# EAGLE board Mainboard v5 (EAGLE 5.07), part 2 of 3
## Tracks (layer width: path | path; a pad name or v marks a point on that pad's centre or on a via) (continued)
GND  (via drill 0.3) (continued)
  Top 0.254: 38.26,59.42 SW2.1 38.31,59.37 v36.99,59.37 | SW1.1 38.26,43.55 v38.26,47.62 38.26,52.12 SW1.2 | R172.1 Q37.E 58.9,41.45 v58.9,40.32 | IC25.2 55.41,136.6 55.41,135.25 | 55.41,135.25 55.41,134.2 IC25.5 | 55.41,135.25 v54.77,135.25 | RESET.2 90.33,112.13 v90.33,113.03 | 98.27,59.69 IC11.2 | Q33.E v54.77,35.88 | IC13.5 60.25,48.49 59.85,48.9 58.9,48.9 58.65,48.65 IC13.3 58.65,46.42 C69.2 v56.67,45.72 | IC13.21 59.45,57.23 C72.2 v58.26,59.69 | C70.2 63.34,59.05 v63.34,60.01 | C135.2 79.53,10.48 v78.58,9.53 | IC37.5 95.81,20.09 95.41,19.68 95.41,18.73 95.66,18.48 IC37.3 98.33,18.48 C137.2 v99.85,18.73 v99.86,18.73 | IC37.21 85.97,19.29 C140.2 | C140.2 D26.2 | C140.2 78.58,20 v75.09,23.5 75.09,24.85 C139.- | C138.2 v85.25,27.3 | C136.2 v95.73,10.16 | v96.05,59.69 98.27,59.69 | v68.74,27.3 IC26.22 | QG1.2 66.82,45.09 v65.56,45.09 | D4.A 83.03,74.16 v83.03,73.03 | C22.2 v2.7,68.9 | IC3.3 v6.19,63.18 | IC4.3 6.53,68.88 7.14,68.26 v7.46,68.26
  Top 0.305: IC1.12 90.97,71.75 v91.6,72.39
  Top 0.406: C80.- 41.61,33.97 v43.34,33.97 | R15.1 IC1.12 | IC7.12 R87.1 | IC2.12 R33.1 v33.5,84.45 | IC5.12 R51.1 v33.5,53.34 | IC6.12 88.11,41.91 R69.1 87.16,40.32 v87.16,39.37
  Top 0.61: v40.16,28.57 40.8,28.57 | 41.12,29.21 R158.1 | v40.16,12.7 41.12,12.7 R168.1 | C23.2 7.46,59.69 ENC2.3 | C34.2 7.46,44.45 ENC3.3 | C11.2 112.88,57.15 ENC1.3 | C45.2 112.88,41.91 ENC4.3 | IC7.12 28.73,112.39 v28.73,111.76 v28.73,108.9
  Top 1.219: C46.A C50.2
  Bottom 0.254: USB.5 77.31,128.91 75.72,128.91 | 75.72,128.91 IC28.2 | 75.72,128.91 73.82,128.91 73.5,129.22 C88.2 73.5,129.86 v73.5,130.81 | C90.2 94.46,124.14 94.46,126.05 | 94.46,126.05 94.46,128.91 94.78,129.22 IC27.10 | 94.46,126.05 IC27.15 | C90.2 v94.78,122.24 92.87,122.24 92.55,122.56 C87.2 | C90.2 | C86.2 90.33,131.13 v89.38,131.13 | C115.2 45.88,29.84 v45.88,29.53 | R159.1 51.59,30.48 51.91,30.48 v51.91,28.89 SJ1.1 | C120.2 45.88,13.97 v45.88,13.65 | R173.1 51.91,14.61 v51.91,13.02 SJ2.1 | IC27.8 90.33,129.86 90.65,130.18 C86.2 | C86.2 | C65.2 v27.15,60.33 | R177.1 73.19,8.25 73.19,8.89 v72.87,9.53 | R179.1 v66.2,8.89 | M2.5 7.83,81.01 8.41,81.6 8.41,87.95 v7.46,88.9 | M3.5 9.32,34.34 8.73,34.92 4.92,34.92 v3.97,33.97 | M1.5 112.51,79.01 111.92,78.42 111.92,73.03 v112.87,72.07 | M4.5 108.38,34.34 107.79,34.92 101.44,34.92 100.49,33.97 v98.58,33.97 C74.2 | 10.32,119.38 C53.2 | v6.19,119.38 10.32,119.38 | C55.2 17.94,119.38 14.13,119.38 | 10.32,119.38 14.13,119.38 | 14.13,119.38 C54.2 | C77.2 15.09,90.72 | v107.47,91.44 106.2,91.44 C73.2 107.47,89.53 107.47,87.95 108.11,87.31 IC15.3 108.13,86.68 105.25,86.68 104.61,87.31 IC14.3 | 25.24,116.84 C76.2 | 25.24,116.84 24.29,117.79 24.29,120.02 | 24.29,120.02 23.45,120.02 IC23.3 | 24.29,120.02 24.29,120.65 24.61,120.97 26.51,120.97 27.15,120.33 IC22.3 | 25.24,116.84 v24.29,116.84 | Q31.E v25.24,131.44 | 97.95,112.08 R144.1 | R145.1 97.95,110.17 | R178.1 70.96,8.57 v70.96,9.53 | IC18.3 25.56,33.97 C75.2 23,35.56 IC19.3 v22.7,33.97 | C68.2 v53.5,56.2 | D21.2 55.72,59.69 55.09,59.69 | 55.09,59.69 v58.26,59.69 | R176.1 v77.63,8.89 | QG2.2 94.15,22.23 v93.5,22.23 | IC17.3 v14.13,89.22 14.13,89.53 C77.2
  Bottom 0.254: IC16.3 16.99,89.22 C77.2 | IC20.3 95.72,35.56 C74.2 | IC21.3 98.9,35.56 C74.2 | v86.84,1.59 C143.2 C142.2 C141.2 | D16.A 84.48,47.31 v83.98,47.31 | D12.A 38.9,48.26 v38.26,47.62 | D20.A v33.81,97.47 | D8.A v36.04,76.2 | C71.- 55.09,61.59 55.09,59.69
  Bottom 0.406: 97.95,111.12 97.95,112.08 | 97.95,111.12 103.03,111.12 JTAG.10 | 97.95,110.17 97.95,111.12
  pour Top (no thermals): 52.55,17.14 52.55,20.64 52.23,20.95 52.23,23.5 53.82,23.5 53.82,22.23 55.09,20.95 55.09,17.14
  pour Top (no thermals): 52.55,1.27 52.55,4.76 52.23,5.08 52.23,7.62 53.82,7.62 53.82,6.35 55.09,5.08 55.09,1.27
  pour Top (no thermals): 79.53,15.88 77.95,15.88 77.63,15.56 77.63,15.24 69.06,15.24 68.42,14.61 68.42,14.29 66.83,14.29 66.83,16.83 68.11,16.83 68.42,17.14 68.42,17.46 69.69,17.46 69.69,17.14 70.01,16.83 74.14,16.83 74.45,17.14 74.45,17.46 77.63,17.46 77.95,17.14 79.53,17.14
  pour Top (no thermals): 10.95,97.47 12.86,97.47 12.86,95.57 14.45,93.98 14.45,92.71 10.32,92.71 10.32,93.66 10.95,94.3
  pour Top (no thermals): 10.95,68.26 10.95,65.41 10,64.45 10,63.5 14.13,63.5 14.13,66.99 12.86,68.26
  pour Top (no thermals): 10.95,55.56 10.95,58.42 10.32,59.05 10.32,60.33 14.13,60.33 14.13,56.83 12.86,55.56
  pour Top (no thermals): 109.06,56.83 109.06,59.69 110.02,60.64 110.02,61.59 105.89,61.59 105.89,56.83
  pour Top (no thermals): 109.06,68.26 109.06,65.41 110.02,64.45 110.02,63.5 105.89,63.5 105.89,68.26
  pour GND (no thermals): 0.16,114.94 8.41,123.19 8.41,31.75 14.77,25.4 14.77,20.95 3.97,20.95 0.16,24.77
  pour GND (no thermals): 9.68,118.11 19.84,118.11 19.84,34.92 33.81,20.95 16.04,20.95 16.04,27.3 9.68,33.66
  pour GND (no thermals): 110.65,70.48 100.49,70.48 100.49,37.47 96.68,33.66 65.56,33.66 52.87,20.95 59.22,20.95 67.47,29.21 103.03,29.21 110.65,36.83
  pour GND (no thermals): 111.92,86.36 119.54,86.36 119.54,24.77 95.41,0.64 66.83,0.64 66.83,5.08 60.48,11.43 60.48,20.32 68.11,27.94 104.3,27.94 111.92,35.56
  pour GND (no thermals): 35.72,20.95 21.11,35.56 21.11,119.38 9.68,119.38 9.68,124.46 24.92,139.7 94.14,139.7 119.54,114.3 119.54,87.63 110.65,87.63 110.65,71.75 99.22,71.75 99.22,38.1 96.68,35.56 64.93,35.56 50.33,20.95
  pour GND (no thermals): 5.24,20.95 25.56,0.64 66.83,0.64 66.83,5.08 59.22,12.7 59.22,20.95
HALL-I1  (via drill 0.3)
  Top 0.254: IC29.26 58,102.3 v57.94,102.23
  Bottom 0.254: v57.94,102.23 57.94,101.6 62.07,101.6 63.66,100.01 63.66,91.76 72.55,82.87 77.31,82.87 82.39,87.95 82.39,94.3 83.34,95.25 83.98,95.25 91.6,87.63 100.49,87.63 100.81,87.31 IC14.4
HALL-I2  (via drill 0.3)
  Top 0.254: IC29.28 57,102.86 v56.99,102.23 | v21.11,88.9 29.37,88.9 39.53,99.06 40.8,100.33 v40.8,102.87
  Bottom 0.254: v56.99,102.23 56.99,102.87 47.78,102.87 47.15,103.5 45.88,103.5 45.24,102.87 v40.8,102.87 | IC16.4 20.8,89.22 v21.11,88.9
HALL-I3  (via drill 0.3)
  Top 0.152: IC29.44 49.86,98.59 49.37,98.11 45.24,98.11 43.66,96.52 v43.34,96.52
  Bottom 0.254: v43.34,96.52 43.34,82.55 42.7,81.92 42.7,48.26 38.58,44.13 37.62,43.18 34.45,43.18 34.45,36.83 31.59,33.97 IC18.4
HALL-I4  (via drill 0.3)
  Top 0.254: v57.94,88.9 57.94,100.33 56.36,101.92 56.36,102.87 56.5,103.02 IC29.29 | v74.45,55.88 82.08,48.26 82.08,41.27 84.93,38.42 v91.6,38.42 | v74.45,76.52 68.74,76.52 v68.11,77.15
  Bottom 0.254: v68.11,77.15 57.94,87.31 v57.94,88.9 | v74.45,55.88 v74.45,76.52 | IC20.4 92.23,35.56 91.6,36.2 v91.6,38.42
HALL-I5  (via drill 0.3)
  Top 0.152: IC29.27 57.5,105.22 v57.31,105.41
  Top 0.254: v42.07,111.76 37.62,116.2 v31.27,116.2
  Bottom 0.254: v57.31,105.41 57.31,111.76 v42.07,111.76 | IC22.4 30.96,120.33 31.27,120.02 v31.27,116.2
JTAG-SRST
  Top 0.254: R143.2 JTAG.15
  Top 0.406: JTAG.15 103.03,106.05 103.03,116.2 109.38,116.2 JP1.1
JTAG-TCK
  Top 0.406: R141.2 JTAG.9
  Bottom 0.406: JTAG.9 R144.2
JTAG-TDI
  Top 0.406: R139.2 JTAG.5
  Bottom 0.406: JTAG.5 R130.1
JTAG-TDO
  Top 0.406: R142.2 JTAG.13
  Bottom 0.406: JTAG.13 R128.1
JTAG-TMS
  Top 0.406: R140.2 JTAG.7
  Bottom 0.406: JTAG.7 R129.1
JTAG-TRST
  Top 0.406: R132.2 JTAG.3 103.03,121.28 109.38,121.28 JP1.2
  Bottom 0.254: JTAG.3 R131.1
KD-CS
  Top 0.254: IC29.139 73.4,99.59 73.82,100.01 77.31,100.01 78.27,100.97 112.56,100.97 KD.7
KD-RST
  Top 0.254: IC29.135 73.94,97.59 74.77,98.42 112.56,98.42 KD.9
LED0
  Top 0.254: LED9.C 49.37,105.31 49.37,104.46 50.01,103.82 50.96,103.82 52.55,102.23 52.55,100.97 52.18,100.59 IC29.40
LED1
  Top 0.254: LED8.C 51.06,105.63 52.23,104.46 53.01,104.46 IC29.36
LIS3I-CS  (via drill 0.3)
  Top 0.254: IC29.47 52.92,97.09 53.5,96.52 53.5,93.03 v54.77,91.76 | v63.98,65.09 63.98,66.04 62.71,67.31 62.39,67.63 61.75,67.63 61.6,67.47 IC24.13
  Bottom 0.254: v54.77,91.76 53.18,90.17 53.18,87.95 54.45,86.68 54.45,85.72 54.45,84.45 53.5,84.45 52.23,83.19 52.23,81.92 53.82,80.33 53.82,78.74 53.5,78.42 53.18,78.11 53.18,72.71 53.18,68.9 56.04,66.04 63.03,66.04 v63.98,65.09
LIS3I-RDY  (via drill 0.3)
  Top 0.254: IC29.81 57,80.66 55.72,79.38 v55.72,73.98 | v55.09,68.26 55.22,68.4 IC24.6
  Bottom 0.254: v55.72,73.98 55.72,68.9 v55.09,68.26
LIS3O-CS  (via drill 0.3)
  Top 0.152: IC29.46 50.13,97.59 50.01,97.47 46.52,97.47 45.88,96.84 44.61,95.57 44.29,95.25
  Top 0.254: 44.29,95.25 42.7,95.25 42.39,95.25 42.07,95.57 42.07,96.2 43.98,98.11 v43.98,116.84 | v61.75,130.18 61.6,130.33 IC25.13
  Bottom 0.254: v43.98,116.84 54.14,116.84 59.22,121.92 59.85,122.56 61.75,124.46 v61.75,130.18
LIS3O-RDY  (via drill 0.3)
  Top 0.254: IC29.140 71.2,100.09 v69.69,101.6 | v55.41,133.35 56.35,133.35 IC25.6
  Bottom 0.254: v69.69,101.6 69.06,102.23 69.06,103.5 73.19,107.63 73.19,120.02 59.85,133.35 v55.41,133.35
M1-A  (via drill 0.3)
  Top 0.61: v100.49,83.19 IC1.26 v95.09,83.19
  Bottom 0.61: M1.11 M1.10 | v100.49,83.19 Q1.2 | v95.09,83.19 94.78,83.19 94.14,83.19 C3.2
  other vias: 110.97,86.04 110.97,85.09 110.97,84.14 106.2,85.72 106.2,84.45 106.2,83.19 106.2,81.92 110.02,86.04 110.02,85.09 110.02,84.14
  pour Top (no thermals): 105.89,86.04 111.28,86.04 111.28,83.82 110.33,83.82 109.7,83.19 109.7,81.6 105.89,81.6
  pour Bottom (no thermals): 114.46,83.82 110.02,83.82 110.02,86.36 113.19,86.36 114.46,85.09
  pour Bottom (no thermals): 101.12,84.77 103.98,84.77 103.98,86.04 106.52,86.04 106.52,81.6 101.12,81.6
M1-ADC  (via drill 0.3)
  Top 0.305: 87.79,69.22 C2.2
  Top 0.61: 102.08,68.26 87.79,68.26 87.79,69.22 87.79,70.48 IC1.13 | v100.55,65.72 101.5,66.67 101.76,66.67 R18.1
  Bottom 0.61: v100.55,65.72 100.17,65.72 99.54,65.09 R91.1
  pour Top (no thermals): 101.12,86.04 105.25,86.04 105.25,65.41 101.44,65.41 101.44,68.26 103.98,68.26 103.98,70.17 101.12,70.17 101.12,73.34 103.67,73.34 103.67,76.52 101.12,76.52 101.12,79.69 103.67,79.69 103.67,82.87 101.12,82.87
M1-AOUT  (via drill 0.3)
  Top 0.254: v89.69,66.99 C58.1 | IC13.24 57.05,57.09 56.36,57.78 56.36,59.69 59.53,62.87 v81.44,62.87
  Bottom 0.254: C58.1 v89.69,66.99 88.74,66.99 84.61,62.87 v81.44,62.87
M1-B  (via drill 0.3)
  Top 0.61: v95.09,78.11 IC1.22 v100.49,78.11
  Bottom 0.61: M1.9 M1.8 | v95.09,78.11 94.46,78.11 94.14,78.11 C4.2 | v100.49,78.11 Q3.3
  other vias: 110.65,82.87 110.65,81.92 110.65,80.96 111.6,82.87 111.6,81.92 106.2,79.38 106.2,78.11 106.2,76.83 106.2,75.56 110.02,80.33
  pour Bottom (no thermals): 110.33,80.01 109.7,80.01 109.7,80.64 110.33,81.28 110.33,83.19 114.46,83.19 114.46,81.92 112.24,81.92
  pour Top (no thermals): 105.89,79.69 108.75,79.69 110.33,81.28 110.33,83.19 111.6,83.19 111.6,77.47 109.38,75.25 105.89,75.25
  pour Bottom (no thermals): 101.12,78.42 103.98,78.42 103.98,79.69 106.52,79.69 106.52,75.25 101.12,75.25
M1-C  (via drill 0.3)
  Top 0.61: v95.09,73.03 IC1.18 100.49,73.03 v100.49,71.75
  Bottom 0.61: v100.49,71.75 Q5.3 | v95.09,73.03 95.09,72.07 C6.2
  other vias: 110.02,73.03 110.02,71.75 110.02,70.48 110.02,69.22 110.97,69.22 110.97,70.48 110.97,71.75 110.97,73.03 106.2,73.03 106.2,71.75 106.2,70.48 106.2,69.22
  pour Bottom (no thermals): 114.46,81.28 114.46,80.01 114.14,79.69 112.24,79.69 111.28,78.74 111.28,68.9 109.7,68.9 109.7,78.42 112.56,81.28
  pour Top (no thermals): 105.89,73.34 111.28,73.34 111.28,68.9 105.89,68.9
  pour Bottom (no thermals): 101.12,72.07 103.98,72.07 103.98,73.34 106.52,73.34 106.52,68.9 101.12,68.9
M1-FLT
  Top 0.254: R4.2 80.49,74.8 D4.C 80.17,74.11 80.17,66.67 82.08,64.77 82.08,62.23 81.44,61.59 76.36,61.59 67.23,52.47 IC13.13
M1-H1  (via drill 0.3)
  Top 0.254: C9.1 R7.1 R12.1 117.63,81.28 117.95,81.6 v117.95,82.55 | IC29.91 62,85.34 v61.75,85.41 | v76.68,78.42 79.53,78.42 83.98,82.87 83.98,86.36 85.25,87.63 v110.02,87.63
  Bottom 0.254: IC15.2 109.38,88.27 v110.02,87.63 112.87,87.63 113.83,86.68 117.95,86.68 v117.95,82.55 | v61.75,85.41 63.34,85.41 70.33,78.42 v76.68,78.42
M1-H2  (via drill 0.3)
  Top 0.254: C10.1 R8.1 R13.1 113.51,86.68 111.92,88.27 v110.65,88.27 84.93,88.27 83.34,86.68 83.34,82.87 79.53,79.06 v76.04,79.06 | IC29.92 62.5,85.84 v62.71,86.04
  Bottom 0.254: v62.71,86.04 63.66,86.04 70.64,79.06 v76.04,79.06 | IC15.1 109.7,89.22 v110.65,88.27
M1-H3  (via drill 0.3)
  Top 0.254: C8.1 R6.1 R9.1 112.24,78.1 112.24,87 v103.03,87 85.57,87 84.61,86.04 84.61,82.87 79.53,77.79 v77.31,77.79 | IC29.93 63,85.07 63.34,85.41 63.34,86.36 v62.71,87
  Bottom 0.254: v62.71,87 62.39,87 61.12,85.72 61.12,85.09 61.75,84.45 63.34,84.45 70.01,77.79 v77.31,77.79 | IC14.1 103.66,89.22 103.03,88.58 v103.03,87
M1-HA  (via drill 0.3)
  Top 0.152: v88.11,90.17 81.44,90.17 79.85,91.76 73.5,91.76 73.17,92.09 IC29.124
  Top 0.406: v87.79,84.45 IC1.2
  Bottom 0.254: v88.11,90.17 88.11,85.09 87.79,84.77 v87.79,84.45
M1-HB  (via drill 0.3)
  Top 0.152: IC29.126 73.44,93.09 74.14,92.39 80.49,92.39 81.44,91.44 v86.84,91.44
  Top 0.406: v87.16,83.19 IC1.3
  Bottom 0.254: v86.84,91.44 86.84,85.72 86.52,85.41 86.52,83.82 v87.16,83.19
M1-HC  (via drill 0.3)
  Top 0.152: IC29.128 73.7,94.09 74.77,93.03 81.12,93.03 81.44,92.71 v85.57,92.71
  Top 0.406: v86.52,81.92 IC1.4
  Bottom 0.254: v85.57,92.71 85.57,86.36 85.25,86.04 85.25,83.19 v86.52,81.92
M1-LA  (via drill 0.3)
  Top 0.152: IC29.125 73.3,92.59 73.82,92.08 80.17,92.08 81.44,90.81 v87.47,90.81
  Top 0.406: v87.79,80.64 IC1.5
  Bottom 0.254: v87.47,90.81 87.47,85.41 87.16,85.09 87.16,84.14 87.79,83.5 v87.79,80.64
M1-LB  (via drill 0.3)
  Top 0.152: IC29.127 73.57,93.59 74.45,92.71 80.81,92.71 81.44,92.08 v86.2,92.08
  Top 0.406: v87.16,79.38 IC1.6
  Bottom 0.254: v86.2,92.08 86.2,86.04 85.89,85.72 85.89,83.5 87.16,82.23 v87.16,79.38
M1-LC  (via drill 0.3)
  Top 0.152: IC29.129 73.84,94.59 75.09,93.34 v84.93,93.34
  Top 0.254: 89.06,78.11 IC1.7
  Top 0.406: v86.52,78.11 89.06,78.11
  Bottom 0.254: v84.93,93.34 84.93,86.68 84.61,86.36 84.61,78.11 v86.52,78.11
M2-A  (via drill 0.3)
  Top 0.61: v24.92,71.75 IC2.26 v19.53,71.75
  Bottom 0.254: M2.10 7.97,76.01
  Bottom 0.61: v24.92,71.75 25.88,71.75 C14.2 | Q7.2 v19.53,71.75
  other vias: 13.81,73.03 13.81,71.75 13.81,70.48 13.81,69.22 10,73.03 10,69.22 10,70.48 10,71.75 9.37,72.39 9.37,73.66
  pour Bottom (no thermals): 5.88,76.2 7.78,76.2 10.32,73.66 10.32,68.9 9.68,68.9 9.68,71.12 5.88,74.93
  pour Bottom (no thermals): 18.89,70.17 16.04,70.17 16.04,68.9 13.5,68.9 13.5,73.34 18.89,73.34
  pour Top (no thermals): 14.13,73.34 14.13,68.9 9.68,68.9 9.68,71.12 9.05,71.75 9.05,74.3 9.68,74.3 10.64,73.34
M2-A1  (via drill 0.3)
  Top 0.254: IC29.10 66,96.96 64.93,95.89 v62.39,95.89 | v47.15,78.74 38.9,70.48 IC2.2
  Bottom 0.254: v62.39,95.89 50.96,95.89 50.33,96.52 49.05,96.52 48.42,95.89 48.42,80.01 v47.15,78.74
M2-A2  (via drill 0.3)
  Top 0.254: IC29.12 65,97.86 64.3,97.16 v62.39,97.16 | v45.88,78.74 38.9,71.75 IC2.3
  Bottom 0.254: v62.39,97.16 50.96,97.16 50.33,97.79 49.05,97.79 47.15,95.89 47.15,80.01 v45.88,78.74
M2-A3  (via drill 0.3)
  Top 0.254: IC29.14 64,98.77 63.66,98.42 v62.39,98.42 | v44.61,78.74 38.9,73.03 IC2.4
  Bottom 0.254: v62.39,98.42 50.96,98.42 50.33,99.06 49.05,99.06 48.42,98.42 45.56,98.42 45.24,98.11 45.24,91.76 44.61,91.12 v44.61,78.74
M2-ADC  (via drill 0.3)
  Top 0.406: 18.57,66.67 v19.84,66.67 19.84,67.94 25.88,67.94 26.2,68.26 | 26.2,68.26 28.42,70.48 28.42,84.45 IC2.13 | C13.2 35.4,68.89 34.45,67.94 32.55,67.94 32.23,68.26 26.2,68.26
  Top 0.61: R36.1 18.2,67.31
  Bottom 0.406: 20.8,66.67 R95.1 20.8,66.67 | 20.8,66.67 v19.84,66.67 20.8,66.67
  pour Top (no thermals): 18.89,84.77 14.77,84.77 14.77,65.41 18.89,65.41 18.89,72.07 16.35,72.07 16.35,75.25 18.89,75.25 18.89,78.42 16.35,78.42 16.35,81.6 18.89,81.6
M2-AOUT  (via drill 0.3)
  Top 0.254: C59.1 v31.59,65.09 34.77,61.91 46.83,61.91 53.88,54.87 IC13.25
  Bottom 0.254: C59.1 v31.59,65.09
M2-B  (via drill 0.3)
  Top 0.61: v24.92,76.83 IC2.22 v19.53,76.83
  Bottom 0.254: M2.8 8.32,78.01 9.68,79.38 | M2.9 8.24,77.01 9.68,75.56
  Bottom 0.61: v24.92,76.83 25.88,76.83 C15.2 | Q9.3 v19.53,76.83
  other vias: 13.81,79.38 13.81,78.11 13.81,76.83 13.81,75.56 10,79.38 10,78.11 10,76.83 10,75.56 9.37,76.2 9.37,77.47 9.37,78.74
  pour Bottom (no thermals): 5.88,78.11 8.41,78.11 10,79.69 10.32,79.69 10.32,75.25 10,75.25 8.41,76.83 5.88,76.83
  pour Bottom (no thermals): 18.89,76.52 16.04,76.52 16.04,75.25 13.5,75.25 13.5,79.69 18.89,79.69
  pour Top (no thermals): 14.13,79.69 14.13,75.25 10,75.25 8.73,76.52 8.73,78.42 10,79.69
M2-B1  (via drill 0.3)
  Top 0.254: IC29.11 65.5,97.41 64.61,96.52 v63.03,96.52 | v47.78,81.28 45.88,81.28 38.9,74.3 IC2.5
  Bottom 0.254: v63.03,96.52 50.96,96.52 50.33,97.16 49.05,97.16 47.78,95.89 v47.78,81.28
M2-B2  (via drill 0.3)
  Top 0.254: IC29.13 64.5,98.32 63.98,97.79 v63.03,97.79 | IC2.6 38.9,75.56 v45.24,81.92
  Bottom 0.254: v63.03,97.79 50.96,97.79 50.33,98.42 49.05,98.42 48.42,97.79 45.88,97.79 45.88,91.76 45.24,91.12 v45.24,81.92
M2-B3  (via drill 0.3)
  Top 0.254: IC29.15 63.5,99.22 63.34,99.06 v63.03,99.06 | IC2.7 38.9,76.83 v43.98,81.92
  Bottom 0.254: v63.03,99.06 50.96,99.06 50.33,99.69 49.05,99.69 48.42,99.06 45.24,99.06 44.61,98.42 44.61,91.76 43.98,91.12 v43.98,81.92
M2-C  (via drill 0.3)
  Top 0.61: v24.92,82.87 23.97,82.87 23.02,81.92 IC2.18 19.53,81.92 v19.53,83.19
  Bottom 0.254: M2.7 8.05,79.01 | M2.6 7.78,80.01 9.68,81.92
  Bottom 0.61: M2.7 M2.6 | v24.92,82.87 C17.2 | Q11.3 v19.53,83.19
  other vias: 13.81,85.72 13.81,84.45 13.81,83.19 13.81,81.92 10,85.72 10,84.45 10,83.19 9.37,82.55 10,81.92 9.37,81.28
  pour Bottom (no thermals): 5.88,80.01 7.78,80.01 9.37,81.6 9.37,85.41 10,86.04 10.32,86.04 10.32,81.28 7.78,78.74 5.88,78.74
  pour Bottom (no thermals): 18.89,82.87 16.04,82.87 16.04,81.6 13.5,81.6 13.5,86.04 18.89,86.04
  pour Top (no thermals): 14.13,81.6 14.13,86.04 10,86.04 10,83.5 9.37,82.87 9.37,80.64 13.18,80.64
M2-FLT  (via drill 0.3)
  Top 0.254: IC13.31 53.28,50.07 47.47,55.88 37.62,55.88 v37.62,57.15
  Bottom 0.254: R22.2 35.54,80.01 D8.C 36.04,80.33 36.35,80.01 37.62,80.01 v37.62,57.15
M2-H1  (via drill 0.3)
  Top 0.254: C20.1 R25.1 R30.1 7.78,78.74 8.1,79.06 8.1,82.87 8.73,83.5 8.73,87.63 v10.95,87.63 29.37,87.63 40.8,99.06 42.07,100.33 v42.07,101.6 | IC29.18 62,102.62 62.39,102.23 v62.39,100.33
  Bottom 0.254: v62.39,100.33 50.96,100.33 49.69,101.6 v42.07,101.6 | v10.95,87.63 11.27,87.31 IC17.1
M2-H2  (via drill 0.3)
  Top 0.254: C21.1 R26.1 R31.1 7.78,74.3 8.1,74.61 8.1,78.42 8.73,79.06 8.73,82.87 9.37,83.5 9.37,87 v18.57,87 29.37,87 v42.7,100.33 | IC29.19 61.5,102.48 61.75,102.23 v61.75,99.69
  Bottom 0.254: v61.75,99.69 50.96,99.69 50.33,100.33 49.05,100.33 48.42,99.69 46.2,99.69 44.93,100.97 43.34,100.97 v42.7,100.33 | IC16.1 18.25,87.31 v18.57,87
M2-H3  (via drill 0.3)
  Top 0.254: C19.1 R24.1 R27.1 7.78,83.19 8.1,83.5 8.1,88.27 v11.59,88.27 29.37,88.27 40.16,99.06 41.44,100.33 v41.44,102.23 | IC29.20 61,102.35 61.12,102.23 v61.12,100.97
  Bottom 0.254: v11.59,88.27 IC17.2 12.86,88.27 | v61.12,100.97 50.96,100.97 49.69,102.23 v41.44,102.23
M3-A  (via drill 0.3)
  Top 0.61: v24.92,40.64 IC5.26 v19.53,40.64
  Bottom 0.61: Q13.2 v19.53,40.64 | v24.92,40.64 25.88,40.64 C26.2
  other vias: 13.81,41.91 13.81,40.64 13.81,39.37 13.81,38.1 13.81,36.83 12.86,36.83 14.77,36.83 13.81,35.88 14.77,35.88
  pour Bottom (no thermals): 15.72,32.38 14.13,32.38 14.13,34.92 11.91,37.15 13.5,37.15 13.5,37.78 16.04,37.78 16.04,36.83 15.72,36.51
  pour Bottom (no thermals): 18.89,39.05 16.04,39.05 16.04,37.78 13.5,37.78 13.5,42.23 18.89,42.23
  pour Top (no thermals): 10.64,42.23 14.13,42.23 14.13,37.78 15.72,36.2 15.72,35.56 13.5,35.56 10.64,38.42
M3-A1  (via drill 0.3)
  Top 0.254: IC29.21 60.5,102.25 59.85,101.6 59.85,95.25 v59.22,94.61
  Top 0.406: IC5.2 32.55,39.37 33.18,40.01 35.09,40.01 v35.72,40.64
  Bottom 0.254: v59.22,94.61 55.72,94.61 50.33,89.22 50.33,79.06 44.61,73.34 44.61,47.31 37.94,40.64 v35.72,40.64
M3-A2  (via drill 0.3)
  Top 0.254: IC29.49 49.58,96.09 v49.37,95.89
  Top 0.406: IC5.3 32.55,40.64 32.86,40.96 34.77,40.96 v35.09,41.27
  Bottom 0.254: v49.37,95.89 49.05,95.57 49.05,79.69 43.34,73.98 43.34,47.94 38.9,43.5 37.94,42.55 35.09,42.55 v35.09,41.27
M3-A3  (via drill 0.3)
  Top 0.152: IC29.53 49.17,94.09 48.74,93.66 v42.07,93.66
  Top 0.406: IC5.4 v33.81,41.91
  Bottom 0.254: v42.07,93.66 42.07,82.55 41.44,81.92 41.44,48.9 38.9,46.35 36.99,46.35 33.81,43.18 v33.81,41.91
M3-ADC  (via drill 0.3)
  Top 0.61: 27.78,53.34 IC5.13 | 27.78,53.34 27.78,55.56 19.84,55.56 19.53,55.88 17.94,55.88 | v19.84,58.42 17.57,58.42 R54.1 | 27.78,53.34 27.78,47.62 26.83,46.67 26.83,38.1 28.1,36.83 31.27,36.83 34.45,36.83 34.77,37.15 C25.2
  Bottom 0.61: R102.1 20.8,58.73 20.48,58.42 v19.84,58.42
  pour Top (no thermals): 18.89,53.66 16.35,53.66 16.35,55.56 18.57,55.56 18.57,58.42 14.77,58.42 14.77,37.78 18.89,37.78 18.89,40.96 16.35,40.96 16.35,44.13 18.89,44.13 18.89,47.31 16.35,47.31 16.35,50.48 18.89,50.48
M3-AOUT  (via drill 0.3)
  Top 0.254: C60.1 v31.91,57.47 35.09,60.64 46.2,60.64 53.57,53.27 IC13.27
  Bottom 0.254: v31.91,57.47 C60.1 30.84,56.96 30.64,57.47 30.77,57.59
M3-B  (via drill 0.3)
  Top 0.61: v24.92,45.72 IC5.22 v19.53,45.72
  Bottom 0.61: v24.92,45.72 25.88,45.72 C27.2 | Q15.3 v19.53,45.72
  other vias: 13.81,48.26 13.81,46.99 13.81,45.72 13.81,44.45 9.68,48.26 9.05,47.62 9.68,46.99 9.05,46.35 9.68,45.72 9.05,45.09 9.68,44.45 12.23,34.92 13.18,34.92 11.91,35.88
  pour Bottom (no thermals): 13.5,32.38 12.23,32.38 12.23,34.92 8.1,39.05 8.1,48.58 10,48.58 10,38.1 13.5,34.61
  pour Bottom (no thermals): 18.89,45.4 16.04,45.4 16.04,44.13 13.5,44.13 13.5,48.58 18.89,48.58
  pour Top (no thermals): 14.13,48.58 8.1,48.58 8.1,45.72 9.68,44.13 14.13,44.13
  pour Top (no thermals): 13.5,34.29 12.23,34.29 12.23,34.92 8.1,39.05 8.1,45.72 10,45.72 10,38.1 13.5,34.61
M3-B1  (via drill 0.3)
  Top 0.254: IC29.22 60,102.39 59.22,101.6 59.22,95.89 v58.58,95.25
  Top 0.406: IC5.5 34.45,43.18 v35.72,41.91
  Bottom 0.254: v58.58,95.25 55.41,95.25 49.69,89.53 49.69,79.38 43.98,73.66 43.98,47.62 38.26,41.91 v35.72,41.91
M3-B2  (via drill 0.3)
  Top 0.152: IC29.50 50.03,95.59 49.69,95.25 49.05,95.25 48.74,95.57 46.52,95.57 45.56,94.61 v41.44,94.61
  Top 0.406: IC5.6 32.86,44.45 v33.18,44.13
  Bottom 0.254: v41.44,94.61 41.44,82.55 40.8,81.92 40.8,49.21 38.58,46.99 36.04,46.99 v33.18,44.13
M3-B3  (via drill 0.3)
  Top 0.152: IC29.54 49.3,93.59 49.05,93.34 43.34,93.34 v42.7,92.71
  Top 0.406: IC5.7 31.59,45.72 32.23,45.09 33.81,45.09 35.09,43.81 v35.72,43.81
  Bottom 0.254: v35.72,43.81 37.31,43.81 42.07,48.58 42.07,81.92 42.7,82.55 v42.7,92.71
M3-C  (via drill 0.3)
  Top 0.61: v24.92,51.75 23.97,51.75 23.02,50.8 IC5.18 19.53,50.8 v19.53,52.07
  Bottom 0.254: M3.6 10.32,34.29
  Bottom 0.61: v24.92,51.75 C29.2 | Q17.3 v19.53,52.07
  other vias: 13.81,54.61 13.81,53.34 13.81,52.07 13.81,50.8 9.68,54.61 9.68,53.34 9.68,52.07 9.68,50.8 9.05,51.44 9.05,52.7 9.05,53.98
  pour Bottom (no thermals): 11.59,32.38 10.32,32.38 10.32,34.29 5.24,39.37 5.24,53.66 6.51,54.93 10.32,54.93 10.32,50.48 7.14,50.48 7.14,39.05 11.59,34.61
  pour Bottom (no thermals): 18.89,51.75 16.04,51.75 16.04,50.48 13.5,50.48 13.5,54.93 18.89,54.93
  pour Top (no thermals): 14.13,50.48 14.13,54.93 8.73,54.93 8.73,50.48
M3-FLT  (via drill 0.3)
  Top 0.254: IC13.32 53.12,49.27 48.42,53.98 41.12,53.98 v40.16,53.02
  Bottom 0.254: D12.C 38.9,53.02 v40.16,53.02
  Bottom 0.406: R40.2 38.4,52.38 D12.C
M3-H1  (via drill 0.3)
  Top 0.254: C32.1 R43.1 R48.1 12.86,32.7 16.99,32.7 v19.84,35.56 v30.32,35.56 | IC29.66 49.02,87.59 48.74,87.31 v40.16,87.31
  Bottom 0.254: v40.16,87.31 40.16,54.61 32.55,54.61 32.55,37.78 v30.32,35.56 | IC19.1 20.8,32.07 19.84,33.02 v19.84,35.56
M3-H2  (via drill 0.3)
  Top 0.254: C33.1 R44.1 R49.1 16.67,31.43 20.16,34.92 27.15,34.92 | 27.15,34.92 v27.15,32.07 | IC29.67 49.47,87.09 49.05,86.68 v39.53,86.68 | 27.15,34.92 v27.47,34.92
  Bottom 0.254: v39.53,86.68 39.53,55.24 31.91,55.24 31.91,38.1 28.73,34.92 v27.47,34.92 | IC18.1 v27.15,32.07
M3-H3  (via drill 0.3)
  Top 0.254: C31.1 R42.1 R45.1 9.05,33.34 16.67,33.34 19.52,36.2 v20.48,36.2 v27.47,36.2 | IC29.68 49.92,86.59 49.37,86.04 v38.9,86.04
  Bottom 0.254: 21.75,33.02 IC19.2 20.48,33.02 v20.48,36.2 | v38.9,86.04 38.9,55.88 31.27,55.88 31.27,38.73 28.73,36.2 v27.47,36.2
M4-A  (via drill 0.3)
  Top 0.61: v100.49,53.34 IC6.26 v95.09,53.34
  Bottom 0.61: M4.11 M4.10 | v100.49,53.34 Q19.2 | v95.09,53.34 93.82,53.34 C37.2
  other vias: 106.2,55.88 106.2,54.61 106.2,53.34 106.2,52.07 110.33,55.88 111.28,55.88 110.33,54.61 111.28,54.61 110.33,53.34 111.28,53.34 110.33,52.07 111.28,52.07
  pour Bottom (no thermals): 114.78,32.38 113.19,32.38 113.19,38.73 112.24,39.69 112.24,51.75 110.02,51.75 110.02,56.2 114.46,56.2 114.46,39.05 114.78,38.73
  pour Top (no thermals): 105.89,56.2 105.89,51.75 114.46,51.75 114.46,56.2
  pour Bottom (no thermals): 101.12,54.93 103.98,54.93 103.98,56.2 106.52,56.2 106.52,51.75 101.12,51.75
M4-A1  (via drill 0.3)
  Top 0.254: v78.27,59.69 83.34,54.61 IC6.2 | IC29.56 52.98,92.59 54.77,90.81 v54.77,89.85 | v68.11,76.2 68.42,75.88 v78.27,75.88
  Bottom 0.254: v78.27,59.69 v78.27,75.88 | v68.11,76.2 54.77,89.53 v54.77,89.85
M4-A2  (via drill 0.3)
  Top 0.152: IC29.87 60,81.44 61.44,80.01 61.44,76.83 62.07,76.2 64.93,76.2 68.42,72.71 73.5,72.71 75.41,70.8 v77.63,70.8
  Top 0.254: v77.63,59.05 83.34,53.34 IC6.3
  Bottom 0.254: v77.63,59.05 v77.63,70.8
M4-A3  (via drill 0.3)
  Top 0.152: IC29.89 61,81.71 62.07,80.64 62.07,77.47 62.71,76.83 65.56,76.83 68.42,73.98 73.5,73.98 75.09,72.39 v77,72.39
  Top 0.254: v77,58.42 83.34,52.07 IC6.4
  Bottom 0.254: v77,58.42 v77,72.39
M4-ADC  (via drill 0.3)
  Top 0.406: C36.2 84.93,57.47 91.28,57.47 93.5,57.47 94.14,56.83
  Top 0.61: IC6.13 91.92,40.64 91.92,52.7 94.14,54.93 94.14,56.83 101.76,56.83 | v100.55,58.42 101.76,58.42 R72.1
  Bottom 0.61: v100.55,58.42 99.86,58.42 99.53,58.74 R105.1
  pour Top (no thermals): 101.12,53.02 101.12,59.69 105.25,59.69 105.25,40.32 101.12,40.32 101.12,43.5 103.67,43.5 103.67,46.67 101.12,46.67 101.12,49.85 103.67,49.85 103.67,53.02
M4-AOUT  (via drill 0.3)
  Top 0.254: v90.97,61.91 C61.1 | IC13.23 57.85,56.93 56.99,57.78 56.99,59.37 59.85,62.23 v80.81,62.23
  Bottom 0.254: C61.1 v90.97,61.91 90.65,62.23 v80.81,62.23
M4-B  (via drill 0.3)
  Top 0.61: v95.09,48.26 IC6.22 v100.49,48.26
  Bottom 0.61: M4.8 M4.9 | v95.09,48.26 94.14,48.26 C38.2 | v100.49,48.26 Q21.3
  other vias: 106.2,49.53 106.2,48.26 106.2,46.99 106.2,45.72 110.33,49.53 110.97,48.9 110.97,47.62 110.33,48.26 110.33,46.99 110.33,45.72 110.97,46.35
  pour Bottom (no thermals): 111.28,32.38 111.28,37.15 110.02,38.42 110.02,49.85 111.28,49.85 111.28,39.37 112.56,38.1 112.56,32.38
  pour Top (no thermals): 105.89,49.85 105.89,45.4 111.28,45.4 111.28,49.85
  pour Bottom (no thermals): 101.12,48.58 103.98,48.58 103.98,49.85 106.52,49.85 106.52,45.4 101.12,45.4
M4-B1  (via drill 0.3)
  Top 0.254: v75.72,57.15 77,57.15 83.34,50.8 IC6.5 | IC29.57 52.21,92.09 52.87,91.44 52.87,90.81 v53.82,89.85 | v75.72,75.25 v68.74,75.25
  Bottom 0.254: v75.72,57.15 v75.72,75.25 | v53.82,89.85 53.82,89.53 62.71,80.64 62.71,77.47 63.03,77.15 66.2,77.15 68.11,75.25 v68.74,75.25
M4-B2  (via drill 0.3)
  Top 0.152: IC29.88 60.5,81.58 61.75,80.33 61.75,77.15 62.39,76.52 65.25,76.52 68.42,73.34 73.5,73.34 75.09,71.75 v76.36,71.75
  Top 0.254: v76.36,56.52 83.34,49.53 IC6.6
  Bottom 0.254: v76.36,56.52 v76.36,71.75
M4-B3  (via drill 0.3)
  Top 0.152: IC29.90 61.5,81.85 62.39,80.96 62.39,77.79 63.03,77.15 65.88,77.15 68.42,74.61 v75.09,74.61
  Top 0.254: v75.09,56.52 83.34,48.26 IC6.7
  Bottom 0.254: v75.09,56.52 v75.09,74.61
M4-C  (via drill 0.3)
  Top 0.61: v95.09,42.23 96.36,42.23 97.31,43.18 IC6.18 100.49,43.18 v100.49,41.91
  Bottom 0.61: M4.7 M4.6 | v95.09,42.23 C40.2 | v100.49,41.91 Q23.3
  other vias: 106.2,43.18 106.2,41.91 106.2,40.64 106.2,39.37 109.06,37.78 109.7,37.15 110.33,36.51 109.06,36.51 108.43,37.15 107.79,37.78
  pour Bottom (no thermals): 109.38,32.38 109.06,32.7 109.06,35.88 106.84,38.1 101.76,38.1 101.12,38.73 101.12,39.05 106.52,39.05 107.16,38.42 109.06,38.42 110.65,36.83 110.65,32.7 110.33,32.38
  pour Top (no thermals): 105.89,43.5 105.89,39.05 106.84,38.1 107.47,38.1 108.43,37.15 109.38,36.2 110.65,36.2 110.65,36.83 109.38,38.1 109.38,43.5
  pour Bottom (no thermals): 101.12,42.23 103.98,42.23 103.98,43.5 106.52,43.5 106.52,39.05 101.12,39.05
M4-FLT  (via drill 0.3)
  Top 0.254: v80.81,60.96 76.68,60.96 67.39,51.67 IC13.12
  Bottom 0.254: R58.2 85.75,50.48 D16.C 85.07,50.8 84.93,50.94 84.93,51.12 80.81,55.24 v80.81,60.96
M4-H1  (via drill 0.3)
  Top 0.254: C43.1 R61.1 R66.1 107.16,36.83 v106.84,36.83 91.92,36.83 91.6,37.15 83.66,37.15 80.81,40.01 80.81,46.99 v73.19,54.61 | IC29.82 57.5,80.52 56.36,79.38 56.36,77.79 59.22,74.93 64.3,74.93 68.42,70.8 v73.19,70.8
  Bottom 0.254: IC21.1 98.81,37.47 106.84,37.47 v106.84,36.83 | v73.19,54.61 v73.19,70.8
M4-H2  (via drill 0.3)
  Top 0.152: IC29.85 59,81.17 60.8,79.38 60.8,76.2 61.44,75.56 64.3,75.56 68.42,71.44 v73.82,71.44
  Top 0.254: C44.1 R62.1 R67.1 115.09,33.98 114.46,34.61 110.02,34.61 107.79,36.83 107.16,37.47 v94.14,37.47 91.92,37.47 91.6,37.78 84.3,37.78 81.44,40.64 81.44,47.62 v73.82,55.24
  Bottom 0.254: IC20.1 95.61,37.47 v94.14,37.47 | v73.82,55.24 v73.82,71.44
M4-H3  (via drill 0.3)
  Top 0.152: IC29.86 59.5,81.31 61.12,79.69 61.12,76.52 61.75,75.88 64.61,75.88 68.42,72.07 v72.55,72.07
  Top 0.254: C42.1 R60.1 R63.1 106.2,34.29 104.3,36.2 v101.12,36.2 91.92,36.2 91.6,36.51 83.03,36.51 80.17,39.37 80.17,46.35 v72.55,53.98
  Bottom 0.254: v72.55,53.98 v72.55,72.07 | IC21.2 100.81,36.51 v101.12,36.2
M5-A  (via drill 0.3)
  Top 0.61: v24.92,100.97 IC7.26 v19.53,100.97
  Bottom 0.61: M5.8 7.14,97.16 8.41,98.42 | v24.92,100.97 25.88,100.97 C48.2 | Q25.2 v19.53,100.97
  other vias: 13.81,102.23 13.81,100.97 13.81,99.69 13.81,98.42 9.68,100.97 9.05,100.33 9.68,99.69 9.68,98.42 9.05,99.06 9.05,97.79 9.68,97.16
  pour Bottom (no thermals): 2.06,97.79 5.88,97.79 10.32,102.23 10.32,96.84 7.78,96.84 7.46,96.52 2.06,96.52 1.75,96.84 1.75,97.47
  pour Bottom (no thermals): 18.89,99.38 16.04,99.38 16.04,98.11 13.5,98.11 13.5,102.55 18.89,102.55
  pour Top (no thermals): 14.13,102.55 10.64,102.55 8.41,100.33 8.41,97.79 9.37,96.84 10.32,96.84 10.32,98.11 14.13,98.11
M5-A1  (via drill 0.3)
  Top 0.254: IC29.141 71.33,100.59 70.33,101.6 70.33,102.23 72.55,104.46 72.55,107 71.92,107.63 v71.92,107.95
  Top 0.406: IC7.2 v35.72,99.69
  Bottom 0.254: v71.92,107.95 71.92,112.39 68.74,115.57 40.8,115.57 35.72,110.49 v35.72,99.69
M5-A2  (via drill 0.3)
  Top 0.254: IC29.1 70.5,104.95 71.92,106.36 71.92,107 71.28,107.63 v71.28,108.58
  Top 0.406: IC7.3 v36.35,100.97
  Bottom 0.254: v71.28,108.58 71.28,112.08 68.42,114.94 41.12,114.94 36.35,110.17 v36.35,100.97
M5-A3  (via drill 0.3)
  Top 0.254: IC29.3 69.5,105.22 70.64,106.36 70.64,107 70.01,107.63 v70.01,108.58
  Top 0.406: IC7.4 v37.62,102.23
  Bottom 0.254: v70.01,108.58 70.01,111.44 67.79,113.67 41.75,113.67 37.62,109.54 v37.62,102.23
M5-ADC  (via drill 0.3)
  Top 0.61: IC7.13 27.78,113.67 27.78,103.5 26.2,101.92 C47.2 25.88,95.56 | 25.88,95.56 C47.2 | 25.88,95.56 25.88,95.89 R90.1 17.3,95.89 | v15.4,94.61 15.4,95.25
  Bottom 0.61: R110.1 20.8,62.87 19.84,61.91 8.41,61.91 8.41,70.17 2.38,70.17 2.38,90.17 6.83,94.61 v15.4,94.61
  pour Top (no thermals): 18.89,113.98 14.77,113.98 14.77,94.61 18.89,94.61 18.89,98.11 18.89,101.28 16.35,101.28 16.35,104.46 18.89,104.46 18.89,107.63 16.35,107.63 16.35,110.81 18.89,110.81
M5-AOUT  (via drill 0.3)
  Top 0.254: C62.1 v31.59,61.28 46.52,61.28 53.72,54.07 IC13.26
  Bottom 0.254: C62.1 30.64,61.59 30.96,61.28 v31.59,61.28
M5-B  (via drill 0.3)
  Top 0.61: v24.92,106.05 IC7.22 v19.53,106.05
  Bottom 0.61: M5.7 4.61,99.69 9.68,104.78 | v24.92,106.05 25.88,106.05 C49.2 | Q27.3 v19.53,106.05
  other vias: 13.81,108.58 13.81,107.31 13.81,106.05 13.81,104.78 9.68,107.95 9.05,107.31 9.68,106.68 9.05,106.05 9.68,105.41 9.05,104.78 9.68,104.14
  pour Bottom (no thermals): 2.06,100.33 4.61,100.33 8.41,104.14 8.41,107.31 10,108.9 10.32,108.9 10.32,103.5 5.88,99.06 2.06,99.06 1.75,99.38 1.75,100.01
  pour Bottom (no thermals): 18.89,105.73 16.04,105.73 16.04,104.46 13.5,104.46 13.5,108.9 18.89,108.9
  pour Top (no thermals): 14.13,104.46 13.5,103.82 9.05,103.82 8.41,104.46 8.41,107.31 10,108.9 14.13,108.9
M5-B1  (via drill 0.3)
  Top 0.254: IC29.142 71.47,101.09 70.96,101.6 70.96,102.23 73.19,104.46 73.19,107 72.55,107.63 v72.55,108.58
  Top 0.406: IC7.5 v35.09,103.5
  Bottom 0.254: v72.55,108.58 72.55,112.71 69.06,116.2 40.48,116.2 35.09,110.81 v35.09,103.5
M5-B2  (via drill 0.3)
  Top 0.254: IC29.2 70,105.09 71.28,106.36 71.28,107 70.64,107.63 v70.64,107.95
  Top 0.406: IC7.6 v36.99,104.78
  Bottom 0.254: v70.64,107.95 70.64,111.76 68.11,114.3 41.44,114.3 36.99,109.86 v36.99,104.78
M5-B3  (via drill 0.3)
  Top 0.254: IC29.4 69,105.36 70.01,106.36 70.01,107 69.38,107.63 v69.38,109.22
  Top 0.406: IC7.7 v38.26,106.05
  Bottom 0.254: v69.38,109.22 69.38,111.12 67.47,113.03 42.07,113.03 38.26,109.22 v38.26,106.05
M5-C  (via drill 0.3)
  Top 0.61: v24.92,112.08 23.97,112.08 23.02,111.12 IC7.18 19.53,111.12 v19.53,112.39
  Bottom 0.61: M5.6 3.97,102.23 | v24.92,112.08 C51.2 | Q29.3 v19.53,112.39
  other vias: 13.81,114.94 13.81,113.67 13.81,112.39 13.81,111.12 9.68,111.76 9.05,112.39 9.68,113.03 9.05,113.67 9.68,114.3 9.05,111.12 9.68,110.49
  pour Bottom (no thermals): 2.06,102.87 3.97,102.87 5.24,104.14 5.24,110.49 10,115.25 10.32,115.25 10.32,110.49 7.78,107.95 7.78,104.78 4.61,101.6 2.06,101.6 1.75,101.92 1.75,102.55
  pour Bottom (no thermals): 18.89,112.08 16.04,112.08 16.04,110.81 13.5,110.81 13.5,115.25 18.89,115.25
  pour Top (no thermals): 14.13,110.81 13.5,110.17 9.05,110.17 8.41,110.81 8.41,113.67 10,115.25 14.13,115.25
M5-FLT  (via drill 0.3)
  Top 0.254: IC13.30 53.43,50.87 47.78,56.52 v38.26,56.52
  Bottom 0.254: R76.2 33.31,93.67 D20.C 33.81,93.03 34.13,92.71 35.09,92.71 38.26,89.53 v38.26,56.52
M5-H1  (via drill 0.3)
  Top 0.152: IC29.5 68.5,102.64 v68.42,102.55
  Top 0.254: v14.13,121.6 R79.1 R84.1 16.04,121.92 16.35,122.24 20.16,122.24 21.11,121.28 21.11,120.33 v21.75,119.7 | v42.7,112.39 37.62,117.47 32.23,117.47 30.32,119.38 22.07,119.38 v21.75,119.7 | v21.75,119.7 21.91,119.54
  Bottom 0.254: v14.13,121.6 R79.1 | v68.42,102.55 68.42,111.12 67.15,112.39 v42.7,112.39 | v21.75,119.7 22.07,119.38 IC23.2
M5-H2  (via drill 0.3)
  Top 0.152: IC29.58 49.85,91.59 48.74,92.71 44.93,92.71 44.29,92.08 v43.98,92.08
  Top 0.254: v17.94,121.6 C55.1 R85.1 20.16,120.33 v21.75,118.75 30.01,118.75 31.91,116.84 v33.81,116.84
  Bottom 0.254: v17.94,121.6 C55.1 | 43.98,94.3 43.98,98.42 35.72,98.42 33.81,100.33 v33.81,116.84 | 43.98,94.3 43.98,93.98 | 43.98,94.3 v43.98,92.08 | IC23.1 22.06,118.43 v21.75,118.75
M5-H3  (via drill 0.3)
  Top 0.152: IC29.59 49.72,91.09 48.42,92.39 45.56,92.39 43.98,90.81 42.7,90.81 v40.16,93.34
  Top 0.254: v10.32,121.6 C53.1 R81.1 12.23,121.92 13.18,122.87 20.48,122.87 21.75,121.6 21.75,120.65 22.38,120.02 v28.73,120.02 30.64,120.02 v32.55,118.11
  Bottom 0.254: C53.1 v10.32,121.6 | v32.55,118.11 32.55,99.69 35.09,97.16 36.35,97.16 v40.16,93.34 | IC22.1 28.1,118.43 28.73,119.06 v28.73,120.02
M-AREF  (via drill 0.3)
  Top 0.254: v60.17,60.01 C72.1 60.25,58.34 IC13.20
  Bottom 0.254: R114.1 57.8,53.34 D21.1 57.63,58.02 59.22,59.6 59.22,61.59 C71.+ 60.17,61.59 v60.17,60.01
M-AVCC  (via drill 0.3)
  Top 0.254: L1.2 61.92,58.57 C70.1 61.85,58.2 IC13.18 61.75,56.27 v61.75,54.93
  Bottom 0.254: v61.75,54.93 61.75,53.66 R114.2
M-CS  (via drill 0.3)
  Top 0.254: IC29.69 52.18,86.09 53.18,85.09 53.18,84.45 50.64,81.92 v50.64,75.56 | IC13.14 65.5,53.27 v65.56,53.34
  Bottom 0.254: v50.64,75.56 50.64,67.63 54.77,63.5 61.75,63.5 65.56,59.69 v65.56,53.34
M-RST  (via drill 0.3)
  Top 0.254: IC29.70 52.04,85.59 52.55,85.09 52.55,84.45 50.01,81.92 v50.01,74.93 | IC13.29 53.58,51.67 v53.5,51.75
  Bottom 0.254: v53.5,51.75 C68.1 | R113.1 v53.5,51.75 | v50.01,74.93 50.01,54.29 52.55,51.75 v53.5,51.75
M-XTAL
  Top 0.254: QG1.3 61.85,45.64 IC13.7
MADC-VOP1  (via drill 0.3)
  Top 0.254: IC9.5 26.2,66.99 25.56,66.36 25.56,64.14 | 25.56,63.2 IC12.5 | 25.56,63.2 25.56,64.14 | IC10.5 25.56,59.39 25.56,60.33 | 25.56,60.33 25.56,61.59 25.88,61.91 25.88,62.55 25.56,62.87 25.56,63.2 | v22.7,63.82 23.02,64.14 25.56,64.14 | v22.7,60.01 23.02,60.33 25.56,60.33
  Bottom 0.254: R106.2 23.02,64.14 v22.7,63.82 | C65.1 23.02,60.33 v22.7,60.01
MADC-VOP2
  Top 0.254: 95.73,63.19 95.73,60.33 95.09,59.69 95.09,58.74 IC11.5 | 95.73,63.19 C66.1 R107.2 | IC8.5 94.79,65.07 95.09,65.09 95.73,64.45 95.73,63.19
N$1  (via drill 0.3)
  Top 0.406: v87.79,75.56 IC1.9
  Bottom 0.254: R5.2 84.93,74.93 87.16,74.93 v87.79,75.56
N$2
  Bottom 0.61: R2.2 Q1.4
N$3  (via drill 0.3)
  Top 0.61: v96.05,84.77 96.05,84.45 IC1.27
  Bottom 0.61: v96.05,84.77 96.05,85.72 R2.1
N$4  (via drill 0.3)
  Top 0.61: v100.49,81.92 Q2.4
  Bottom 0.61: R3.2 v100.49,81.92
N$5  (via drill 0.3)
  Top 0.61: v96.05,79.38 IC1.23
  Bottom 0.61: v96.05,79.38 R10.1
N$6
  Bottom 0.254: R120.1 BD.5
N$7
  Top 0.254: Q37.B R172.2 R166.2
N$8  (via drill 0.3)
  Top 0.254: v113.51,73.66 R9.2
  Bottom 0.254: v113.51,73.66 114.78,73.66 114.78,75.56 114.33,76.01 M1.2
N$9  (via drill 0.3)
  Top 0.254: R12.2 113.51,78.42 113.83,78.11 v115.41,78.11
  Bottom 0.254: M1.3 114.32,77.01 v115.41,78.11
N$10  (via drill 0.3)
  Top 0.254: v115.09,82.55 113.83,82.55 113.51,82.87 R13.2
  Bottom 0.254: M1.4 114.36,78.01 115.09,78.74 v115.09,82.55
N$11
  Bottom 0.61: R10.2 Q3.4
N$12  (via drill 0.3)
  Top 0.61: IC1.15 93.19,69.22 v93.19,75.56
  Bottom 0.61: v93.19,75.56 R14.1
N$13  (via drill 0.3)
  Top 0.61: v100.49,75.56 Q4.4
  Bottom 0.61: R14.2 v100.49,75.56
N$14  (via drill 0.3)
  Top 0.254: v47.15,47.31 LED20.C
  Bottom 0.254: R210.2 58.58,48.9 55.41,45.72 48.74,45.72 v47.15,47.31
N$15
  Bottom 0.254: R119.1 BD.4
N$16  (via drill 0.3)
  Top 0.61: v96.05,74.3 IC1.19
  Bottom 0.61: v96.05,74.3 96.05,73.03 R16.1
N$17
  Bottom 0.61: R16.2 99.22,73.34 99.54,73.03 Q5.4
N$18  (via drill 0.3)
  Top 0.61: IC1.14 v91.6,69.22
  Bottom 0.61: v91.6,69.22 97,69.22 R17.1
N$19  (via drill 0.3)
  Top 0.61: v100.49,69.22 Q6.4
  Bottom 0.61: R17.2 99.22,69.22 v100.49,69.22
N$20
  Bottom 0.254: R121.1 BD.6
N$21  (via drill 0.3)
  Top 0.254: v49.05,47.31 LED21.C
  Bottom 0.254: R211.2 55.09,46.35 50.01,46.35 v49.05,47.31
N$22
  Bottom 0.254: R115.2 KD.1
N$23
  Bottom 0.254: R116.2 KD.3
N$24
  Bottom 0.254: R117.1 KD.5
N$25
  Top 0.254: LED8.A R150.1
N$26
  Top 0.406: R196.1 LED10.A
N$27
  Bottom 0.61: BUZZ.+ 33.81,127.3 33.65,127.47 | 33.65,127.47 D22.C | R118.1 33.65,127.78 33.65,127.47
N$28
  Bottom 0.61: 26.2,127.3 D22.A | BUZZ.- 26.2,127.3 | Q31.C 25.69,127.81 26.2,127.3
N$29
  Bottom 0.61: Q31.B 23.19,129.85 R122.2
N$30
  Top 0.406: R197.1 LED11.A
N$31
  Top 0.406: R198.1 LED12.A
N$32
  Top 0.406: R199.1 LED13.A
N$33  (via drill 0.3)
  Top 0.61: v95.09,85.72 IC1.28
  Bottom 0.61: v95.09,85.72 94.78,85.72 94.14,85.72 C3.1 93.5,85.72 91.81,85.72 D1.C
N$34  (via drill 0.3)
  Top 0.61: v23.97,75.56 IC2.23
  Bottom 0.61: R28.1 v23.97,75.56
N$35  (via drill 0.3)
  Top 0.61: IC1.24 96.05,80.64 v95.09,79.69
  Bottom 0.61: D2.C 91.6,79.69 C4.1 v95.09,79.69
N$36  (via drill 0.3)
  Top 0.61: IC2.15 27.15,85.72 27.15,79.38 v26.83,79.38
  Bottom 0.61: R32.1 v26.83,79.38
N$37  (via drill 0.3)
  Top 0.61: IC1.20 95.09,75.56 v95.09,74.3
  Bottom 0.61: C6.1 91.6,73.97 D3.C | C6.1 93.82,74.3 | v95.09,74.3 94.14,74.3 C6.1
N$38  (via drill 0.3)
  Top 0.61: IC2.19 v23.97,80.64
  Bottom 0.61: v23.97,80.64 23.97,81.92 R34.1
N$39  (via drill 0.3)
  Top 0.61: IC1.16 94.14,70.48 94.14,80.01 v94.14,80.96
  Bottom 0.61: v94.14,80.96 96.36,80.96 R3.1
N$40  (via drill 0.3)
  Top 0.61: v28.73,85.72 IC2.14
  Bottom 0.61: R35.1 v28.73,85.72
N$41  (via drill 0.3)
  Top 0.61: IC2.28 v24.92,69.22
  Bottom 0.61: v24.92,69.22 25.56,69.22 C14.1 28.62,69.85 D5.C
N$42  (via drill 0.3)
  Top 0.61: IC2.24 23.97,74.3 v24.92,75.25
  Bottom 0.61: v24.92,75.25 C15.1 28.3,75.25 D6.C
N$43  (via drill 0.3)
  Top 0.61: IC2.20 24.92,79.38 v24.92,80.96
  Bottom 0.61: v24.92,80.96 C17.1 28.3,80.97 D7.C
N$44  (via drill 0.3)
  Top 0.61: IC2.16 25.88,84.45 25.88,79.38 25.88,74.3 v25.88,73.98
  Bottom 0.61: v25.88,73.98 23.65,73.98 R21.1
N$45
  Top 0.406: 35.4,81.92 R29.1 | 35.4,81.92 R33.2 | IC2.11 35.4,81.92
N$46
  Top 0.406: R15.2 84.94,73.03 | 84.94,73.03 R11.1 | 84.94,73.03 IC1.11
N$47  (via drill 0.3)
  Top 0.254: IC13.9 62.77,49.27 v62.71,49.21
  Bottom 0.254: v62.71,49.21 62.39,48.9 R210.1
N$48
  Top 0.254: FLT2.C 35.4,88.17
  Top 0.406: 35.4,88.17 R19.1
N$49  (via drill 0.3)
  Top 0.61: IC2.27 23.97,70.48 v23.97,70.17
  Bottom 0.61: v23.97,70.17 23.97,69.22 R20.1
N$50  (via drill 0.3)
  Top 0.254: IC13.10 63.44,50.07 v62.71,50.8
  Bottom 0.254: v62.71,50.8 R211.1
N$51
  Top 0.406: R1.1 85.25,77.15 85.25,82.77 FLT1.C
N$52
  Top 0.406: IC2.9 32.23,79.38 R23.2
N$53  (via drill 0.3)
  Top 0.61: v23.97,44.45 IC5.23
  Bottom 0.61: R46.1 v23.97,44.45
N$54  (via drill 0.3)
  Top 0.61: IC5.15 26.83,54.61 v26.83,48.26
  Bottom 0.61: R50.1 v26.83,48.26
N$55  (via drill 0.3)
  Top 0.61: IC5.19 v23.97,49.53
  Bottom 0.61: v23.97,49.53 23.97,50.8 R52.1
N$56  (via drill 0.3)
  Top 0.61: v28.73,54.61 IC5.14
  Bottom 0.61: R53.1 v28.73,54.61
N$57  (via drill 0.3)
  Top 0.61: IC5.28 v24.92,38.1
  Bottom 0.61: v24.92,38.1 25.88,38.1 C26.1 26.52,38.1 28.1,38.1 28.3,38.3 D9.C
N$58  (via drill 0.3)
  Top 0.61: IC5.24 23.97,43.18 v24.92,44.13
  Bottom 0.61: v24.92,44.13 C27.1 28.42,44.13 D10.C
N$59  (via drill 0.3)
  Top 0.61: IC5.20 24.92,48.26 v24.92,49.85
  Bottom 0.61: v24.92,49.85 C29.1 28.42,49.85 D11.C
N$60  (via drill 0.3)
  Top 0.61: IC5.16 25.88,53.34 v25.88,42.86
  Bottom 0.61: v25.88,42.86 23.66,42.86 R39.1
N$61
  Top 0.406: 35.4,50.8 R47.1 | 35.4,50.8 R51.2 | IC5.11 35.4,50.8
N$63
  Top 0.406: FLT3.C 32.77,33.76 R37.1
N$64  (via drill 0.3)
  Top 0.61: IC5.27 23.97,39.37 v23.97,39.05
  Bottom 0.61: v23.97,39.05 23.97,38.1 R38.1
N$65
  Top 0.406: IC5.9 32.23,48.26 R41.2
N$66  (via drill 0.3)
  Top 0.61: v96.05,49.53 IC6.23
  Bottom 0.61: v96.05,49.53 R64.1
N$67  (via drill 0.3)
  Top 0.61: IC6.15 93.5,39.37 93.19,39.37 v93.19,45.72
  Bottom 0.61: v93.19,45.72 R68.1
N$68  (via drill 0.3)
  Top 0.61: v96.05,44.45 IC6.19
  Bottom 0.61: v96.05,44.45 96.05,43.18 R70.1
N$69  (via drill 0.3)
  Top 0.61: IC6.14 v91.6,39.37
  Bottom 0.61: v91.6,39.37 R71.1
N$70  (via drill 0.3)
  Top 0.61: v95.09,55.88 IC6.28
  Bottom 0.61: 93.82,55.88 v95.09,55.88 | 93.82,55.88 C37.1 93.82,55.88 | 93.82,55.88 92.23,55.88 92.23,55.67 D13.C
N$71  (via drill 0.3)
  Top 0.61: IC6.24 96.05,50.8 v95.09,49.85
  Bottom 0.61: v95.09,49.85 C38.1 91.72,49.84 D14.C
N$72  (via drill 0.3)
  Top 0.61: IC6.20 95.09,45.72 v95.09,44.13
  Bottom 0.61: v95.09,44.13 C40.1 91.72,44.13 D15.C
N$73  (via drill 0.3)
  Top 0.61: IC6.16 94.14,40.64 v94.14,51.12
  Bottom 0.61: v94.14,51.12 96.36,51.12 R57.1
N$74
  Top 0.406: IC6.11 R65.1 86.52,42.87 86.52,42.55 84.94,40.96 R69.2
N$76  (via drill 0.3)
  Top 0.254: v5.24,63.18 IC3.2
  Bottom 0.254: ENC2.2 3.97,57.15 5.24,58.42 v5.24,63.18
N$77
  Top 0.254: ENC2.4 6.19,62.23 7.14,63.18 7.14,67.31 6.51,67.94 5.24,67.94 IC4.2
N$78  (via drill 0.3)
  Top 0.254: IC35.3 68.41,11.42 C121.1 v68.11,9.53
  Bottom 0.254: C121.1 v68.1,9.53 v68.11,9.53
N$79  (via drill 0.3)
  Top 0.254: IC31.6 48.78,28.26 v49.37,28.26
  Bottom 0.254: v49.37,28.26 50.01,27.62 SJ1.2
N$80
  Top 0.406: R55.1 97,32.06 95.41,30.48 95.41,30.26 FLT4.C
N$82
  Top 0.406: SW3.2 26.51,21.91 32.55,27.94 F1.P$2
  pour Top (no thermals): 23.02,22.86 23.02,20.95 24.29,19.68 25.56,19.68 33.81,27.94 33.81,30.48 33.18,31.11 31.91,31.11 31.27,30.48 31.27,29.84 25.56,24.13 24.29,24.13
N$83  (via drill 0.3)
  Top 0.61: IC6.27 96.05,54.61 v96.05,54.93
  Bottom 0.61: v96.05,54.93 96.05,55.88 R56.1
N$84  (via drill 0.3)
  Top 0.254: IC36.12 74.44,19.06 75.41,20 C132.1 v75.72,21.59
  Bottom 0.254: C132.1 v75.72,21.59
N$85  (via drill 0.3)
  Top 0.254: IC36.14 IC36.13 73.82,18.41 v73.82,17.46
  Bottom 0.254: v73.82,17.46 R187.1
N$86
  Top 0.406: R59.2 IC6.9
N$87  (via drill 0.3)
  Top 0.254: v75.72,9.53 C134.1 75.73,11.11 75.72,11.11 C134.1 74.45,12.06 74.44,12.08 IC36.3
  Bottom 0.254: v75.72,9.53 75.72,11.11 C134.1
N$88  (via drill 0.3)
  Top 0.254: IC36.1 IC36.2 73.82,12.7 v73.82,13.65
  Bottom 0.254: v73.82,13.65 73.82,14.29 78.58,14.29 81.44,11.43 81.44,9.21 82.71,7.94 R188.1
N$89  (via drill 0.3)
  Top 0.61: IC7.23 v23.97,104.78
  Bottom 0.61: v23.97,104.78 R82.1
N$90  (via drill 0.3)
  Top 0.254: C135.1 77.95,11.11 v77.95,12.06 | IC36.5 75.72,12.62 v75.72,13.65
  Bottom 0.254: C135.1 77.95,11.11 v77.95,12.06 75.72,12.06 v75.72,13.65
N$91  (via drill 0.3)
  Top 0.254: IC36.6 IC36.7 77,12.7 v77,13.65
  Bottom 0.254: v77,13.65 78.58,13.65 80.81,11.43 80.81,7.94 82.71,6.03 R189.1
N$92  (via drill 0.3)
  Top 0.61: IC7.15 26.83,114.94 v26.83,108.58
  Bottom 0.61: R86.1 v26.83,108.58
N$93  (via drill 0.3)
  Top 0.61: v23.97,109.86 IC7.19
  Bottom 0.61: v23.97,109.86 23.97,111.12 R88.1
N$94
  Top 0.406: R200.1 LED14.A
N$95  (via drill 0.3)
  Top 0.61: v28.42,114.94 IC7.14
  Bottom 0.61: R89.1 v28.42,114.94
N$96  (via drill 0.3)
  Top 0.61: IC7.28 v24.92,98.42
  Bottom 0.61: v24.92,98.42 25.88,98.42 C48.1 28.42,98.75 D17.C
N$97  (via drill 0.3)
  Top 0.61: IC7.24 23.97,103.5 v24.92,104.46
  Bottom 0.61: v24.92,104.46 C49.1 28.28,104.46 D18.C
N$98
  Top 0.254: LED15.A
  Top 0.406: R201.1 LED15.A
N$99  (via drill 0.3)
  Top 0.61: IC7.20 24.92,108.58 v24.92,110.17
  Bottom 0.61: v24.92,110.17 C51.1 28.28,110.17 D19.C
N$100
  Bottom 0.61: Q7.4 R20.2
N$101
  Top 0.254: Q33.C 50.33,34.92 49.37,33.97 R124.1
N$102
  Top 0.254: R123.1 48.42,38.73 Q32.C
N$103
  Top 0.406: R202.1 LED16.A
N$104
  Top 0.254: LED17.A
  Top 0.406: R203.1 LED17.A
N$105
  Bottom 0.254: IC14.2 104.62,88.27 105.57,87.31 IC15.4
N$106
  Bottom 0.254: IC16.2 16.67,88.27 15.72,89.22 IC17.4
N$107
  Bottom 0.254: IC18.2 25.24,33.02 24.29,33.97 IC19.4
N$108
  Bottom 0.254: IC20.2 95.73,36.51 96.68,35.56 IC21.4
N$109
  Bottom 0.254: IC22.2 26.83,119.38 25.88,120.33 IC23.4
N$110
  Top 0.406: R204.1 LED18.A
N$111
  Top 0.406: R205.1 LED19.A
N$112
  Top 0.254: IC37.30 93.44,14.04 94.14,13.34 97.86,13.34 LED10.C
N$113
  Top 0.254: R123.2 46.83,40.96 46.83,41.27 DATA.C
N$114
  Top 0.254: R124.2 46.83,35.88 46.52,36.2 CFG.C
N$115  (via drill 0.3)
  Top 0.254: IC34.6 48.78,12.38 v49.37,12.38
  Bottom 0.254: v49.37,12.38 50.01,11.75 SJ2.2
N$116  (via drill 0.3)
  Top 0.254: IC35.1 IC35.2 67.79,12.7 v67.79,13.65
  Bottom 0.254: v67.79,13.65 67.79,15.56 78.58,15.56 82.39,11.75 R181.1
N$117
  Top 0.406: R23.1 35.09,78.42 35.09,78.74 33.5,80.33 R29.2 IC2.10
N$118  (via drill 0.3)
  Top 0.254: IC35.5 69.71,11.42 C122.1 arc90 C122.1 v70.01,9.53
  Bottom 0.254: v70.01,9.53 C122.1
N$119  (via drill 0.3)
  Top 0.254: 70.33,12.7 IC35.6 | 70.33,12.7 v70.33,13.65 | 70.33,12.7 70.95,12.7 IC35.7
  Bottom 0.254: v70.33,13.65 70.33,14.92 78.58,14.92 82.08,11.43 82.08,10.48 82.71,9.84 R183.1
N$120
  Top 0.254: LED9.A R151.1
N$121  (via drill 0.3)
  Top 0.61: Q8.4 v19.53,73.03
  Bottom 0.61: v19.53,73.03 R21.2
N$122  (via drill 0.3)
  Top 0.254: IC35.10 69.71,19.7 C123.1 v70.01,21.59
  Bottom 0.254: v70.01,21.59 C123.1
N$123  (via drill 0.3)
  Top 0.254: 70.33,18.41 IC35.9 | v70.33,17.46 70.33,18.41 | 70.33,18.41 70.39,18.48 IC35.8
  Bottom 0.254: v70.33,17.46 70.33,16.83 78.58,16.83 79.85,15.56 R184.1
N$124  (via drill 0.3)
  Top 0.254: v5.56,86.36 R27.2
  Bottom 0.254: M2.2 6,84.01 5.56,84.45 v5.56,86.36
N$125  (via drill 0.3)
  Top 0.254: IC35.12 68.41,19.7 C131.1 v68.11,21.59
  Bottom 0.254: C131.1 v68.11,21.59
N$126  (via drill 0.3)
  Top 0.254: IC35.14 IC35.13 67.79,18.41 v67.79,17.46
  Bottom 0.254: v67.79,17.46 67.79,16.19 78.58,16.19 81.12,13.65 R185.1
N$127  (via drill 0.3)
  Top 0.254: v5.24,77.47 5.56,77.47 6.19,76.83 R31.2
  Bottom 0.254: M2.4 6.29,82.01 5.24,80.96 v5.24,77.47
N$128
  Top 0.406: IC5.10 R47.2 33.5,49.21 35.09,47.62 35.09,47.3 R41.1
N$129
  Top 0.406: R65.2 84.94,44.45 | 84.94,44.45 R59.1 | 84.94,44.45 IC6.10
N$130  (via drill 0.3)
  Top 0.254: C56.1 v96.05,66.99 97.01,67.01 IC8.3
  Bottom 0.254: v96.05,66.99 C56.1
N$131  (via drill 0.3)
  Top 0.254: R93.1 93.19,66.99 v94.14,66.04 94.14,66.36 IC8.4
  Bottom 0.254: R93.1 93.19,66.99 v94.14,66.04
N$132  (via drill 0.3)
  Top 0.254: v96.05,65.09 IC8.1
  Bottom 0.254: v96.05,65.09 R93.2 R94.1
N$133  (via drill 0.3)
  Top 0.254: C57.1 v22.38,64.77 22.7,65.09 IC9.3
  Bottom 0.254: C57.1 v22.38,64.77
N$134  (via drill 0.3)
  Top 0.254: R100.1 28.1,65.09 v27.15,66.04 27.15,65.72 IC9.4
  Bottom 0.254: R100.1 28.1,65.09 v27.15,66.04
N$135  (via drill 0.3)
  Top 0.254: IC9.1 v25.24,66.99
  Bottom 0.254: v25.24,66.99 R100.2 R96.1
N$136  (via drill 0.3)
  Top 0.254: C63.1 v22.38,57.15 22.7,57.47 IC10.3
  Bottom 0.254: C63.1 v22.38,57.15
N$137  (via drill 0.3)
  Top 0.254: R104.1 28.1,57.47 v27.15,58.42 27.15,58.1 IC10.4
  Bottom 0.254: R104.1 28.1,57.47 v27.15,58.42
N$138  (via drill 0.3)
  Top 0.254: IC10.1 24.61,59.37 v25.24,58.74
  Bottom 0.254: v25.24,58.74 25.56,59.05 28.1,59.05 R104.2 R97.1
N$139  (via drill 0.3)
  Top 0.254: C64.1 98.27,61.59 v97.95,61.59 97.95,60.96 97.63,60.64 97.65,60.66 IC11.3
  Bottom 0.254: v97.95,61.59 98.27,61.59 C64.1
N$140  (via drill 0.3)
  Top 0.254: R109.1 93.19,60.64 v94.14,59.69 94.14,60.01 IC11.4
  Bottom 0.254: R109.1 93.19,60.64 v94.14,59.69
N$141  (via drill 0.3)
  Top 0.254: v96.05,58.74 IC11.1 97.63,58.74
  Bottom 0.254: v96.05,58.74 R109.2 R98.1
N$142  (via drill 0.3)
  Top 0.254: C67.1 v22.38,60.96 22.7,61.28 IC12.3
  Bottom 0.254: v22.38,60.96 C67.1
N$143  (via drill 0.3)
  Top 0.254: R112.1 28.1,61.28 v27.15,62.23 27.15,61.91 IC12.4
  Bottom 0.254: R112.1 28.1,61.28 v27.15,62.23
N$144  (via drill 0.3)
  Top 0.254: IC12.1 24.29,63.18 v25.24,62.23
  Bottom 0.254: v25.24,62.23 25.88,62.87 28.1,62.87 R112.2 R101.1
N$145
